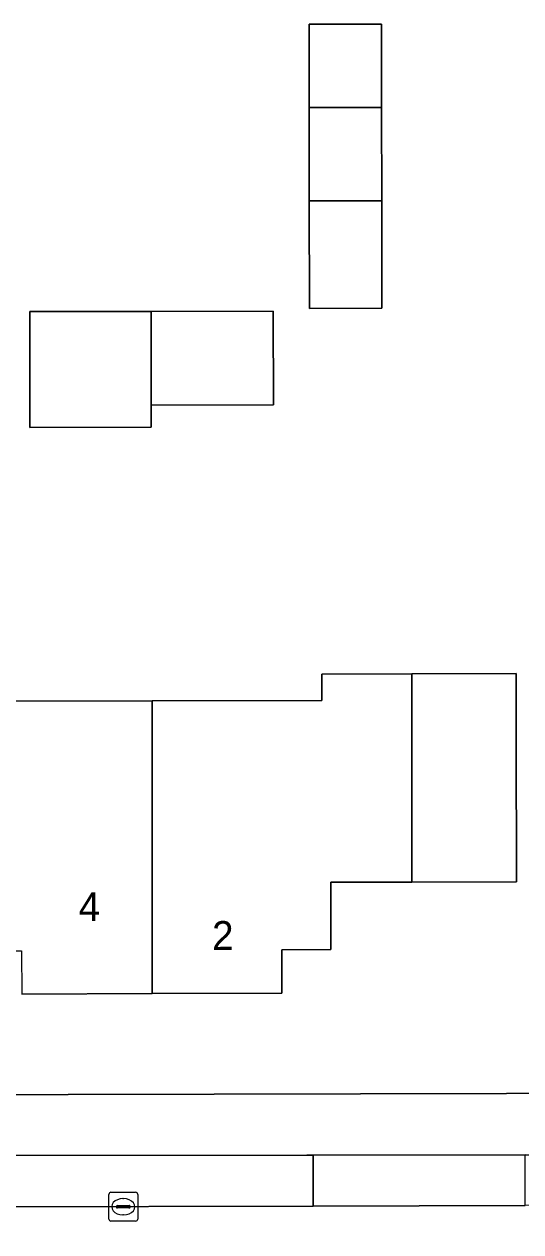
# Model space of a CAD drawing. Extents: x 160455 to 162082, y 388339 to 389736.
# Drawn here: x 160972.91 to 160990.1, y 388459.2 to 388501.02 of the extents above; entities that cross this region are included whole.
import ezdxf

# ---------------------------------------------------------------- set-up
doc = ezdxf.new("R2010")
doc.units = 0
for name, color, linetype in [('IMGEO_Erf', 7, 'Continuous'), ('IMGEO_Kolk', 7, 'Continuous'), ('IMGEO_Muur', 7, 'Continuous'), ('IMGEO_Pand', 7, 'Continuous'), ('IMGEO_Pand_nummerreeks', 7, 'Continuous'), ('IMGEO_Parkeervlak_open', 7, 'Continuous'), ('IMGEO_Rijbaan_lokaal_open', 7, 'Continuous'), ('IMGEO_Voetpad_open', 7, 'Continuous')]:
    doc.layers.add(name, color=color, linetype=linetype)

msp = doc.modelspace()

# ---------------------------------------------------------------- linework, layer by layer
at = {"layer": 'IMGEO_Erf'}
for points in [[(160985.287, 388494.904), (160985.293, 388491.181), (160982.786, 388491.177), (160982.78, 388494.904), (160982.775, 388498.125), (160982.772, 388501.016), (160985.279, 388501.016), (160985.282, 388498.128)], [(160981.536, 388491.078), (160981.541, 388487.832), (160977.31, 388487.826), (160977.311, 388487.063), (160973.113, 388487.056), (160973.107, 388491.065), (160977.305, 388491.072)]]:
    msp.add_lwpolyline(points, close=True, dxfattribs=at)
for points in [[(160971.454, 388477.577), (160977.344, 388477.591), (160983.214, 388477.605), (160983.212, 388478.515), (160986.332, 388478.522), (160989.942, 388478.531), (160989.947, 388476.322), (160989.959, 388471.322), (160986.334, 388471.314), (160983.525, 388471.308), (160983.527, 388468.978), (160981.825, 388468.971), (160981.831, 388467.473), (160977.341, 388467.452), (160972.831, 388467.431)], [(160954.202, 388463.916), (160989.602, 388463.995), (161000.033, 388464.037), (161013.406, 388464.055)]]:
    msp.add_lwpolyline(points, dxfattribs=at)
at = {"layer": 'IMGEO_Kolk'}
for p, q in [((160975.917, 388460.575), (160976.769, 388460.575)), ((160975.842, 388459.649), (160975.842, 388460.501)), ((160976.144, 388460.118), (160976.542, 388460.118)), ((160976.33, 388460.355), (160976.355, 388460.355)), ((160976.843, 388460.501), (160976.843, 388459.649)), ((160976.101, 388460.069), (160976.101, 388460.081)), ((160976.539, 388460.032), (160976.141, 388460.032)), ((160976.353, 388459.795), (160976.328, 388459.795)), ((160976.585, 388460.081), (160976.585, 388460.069)), ((160976.769, 388459.575), (160975.917, 388459.575))]:
    msp.add_line(p, q, dxfattribs=at)
for points in [[(160975.917, 388460.575), (160976.769, 388460.575)], [(160975.842, 388459.649), (160975.842, 388460.501)], [(160976.843, 388460.501), (160976.843, 388459.649)], [(160976.769, 388459.575), (160975.917, 388459.575)]]:
    msp.add_lwpolyline(points, dxfattribs=at)
for centre, radius, start, end in [((160975.919, 388460.499), 0.0765, 91.552, 178.448), ((160975.919, 388460.499), 0.0765, 91.552, 178.448), ((160976.767, 388460.499), 0.0765, 1.552, 88.448), ((160976.767, 388460.499), 0.0765, 1.552, 88.448), ((160976.141, 388460.078), 0.0403, 85.8775, 175.7526), ((160976.546, 388460.08), 0.0386, 1.7309, 96.639), ((160976.138, 388460.068), 0.0366, 178.938, 274.7102), ((160976.542, 388460.075), 0.043, 264.8664, 352.4533), ((160975.919, 388459.651), 0.0765, 181.552, 268.448), ((160975.919, 388459.651), 0.0765, 181.552, 268.448), ((160976.767, 388459.651), 0.0765, 271.552, 358.448), ((160976.767, 388459.651), 0.0765, 271.552, 358.448)]:
    msp.add_arc(centre, radius, start, end, dxfattribs=at)
for centre, major_axis, ratio, start_param, end_param in [((160976.329, 388460.075), (-0.387, 0.002), 0.722429, 4.712389, 7.853982), ((160976.354, 388460.075), (-0.39, 0.002), 0.717154, 1.570796, 4.712389)]:
    msp.add_ellipse(centre, major_axis=major_axis, ratio=ratio, start_param=start_param, end_param=end_param, dxfattribs=at)
at = {"layer": 'IMGEO_Muur'}
msp.add_lwpolyline([(160989.602, 388463.995), (161000.033, 388464.037)], dxfattribs=at)
at = {"layer": 'IMGEO_Pand'}
for points in [[(160985.282, 388498.128), (160985.279, 388501.016), (160982.772, 388501.016), (160982.775, 388498.125)], [(160985.282, 388498.128), (160982.775, 388498.125), (160982.78, 388494.904), (160985.287, 388494.904)], [(160985.287, 388494.904), (160982.78, 388494.904), (160982.786, 388491.177), (160985.293, 388491.181)], [(160977.305, 388491.072), (160973.107, 388491.065), (160973.113, 388487.056), (160977.311, 388487.063), (160977.31, 388487.826)], [(160977.305, 388491.072), (160977.31, 388487.826), (160981.541, 388487.832), (160981.536, 388491.078)], [(160977.341, 388467.452), (160981.831, 388467.473), (160981.825, 388468.971), (160983.527, 388468.978), (160983.525, 388471.308), (160986.334, 388471.314), (160986.332, 388478.522), (160983.212, 388478.515), (160983.214, 388477.605), (160977.344, 388477.591)], [(160989.947, 388476.322), (160989.942, 388478.531), (160986.332, 388478.522), (160986.334, 388471.314), (160989.959, 388471.322)], [(160968.321, 388478.469), (160968.337, 388471.234), (160971.125, 388471.225), (160971.125, 388468.933), (160972.825, 388468.939), (160972.831, 388467.431), (160977.341, 388467.452), (160977.344, 388477.591), (160971.454, 388477.577), (160971.451, 388478.476), (160970.191, 388478.473)]]:
    msp.add_lwpolyline(points, close=True, dxfattribs=at)
at = {"layer": 'IMGEO_Parkeervlak_open'}
for points in [[(160982.914, 388461.859), (160982.699, 388461.859), (160971.824, 388461.853), (160971.515, 388461.851), (160971.515, 388460.073), (160982.917, 388460.099)], [(160990.248, 388461.875), (160982.914, 388461.859), (160982.917, 388460.099), (160990.252, 388460.115)]]:
    msp.add_lwpolyline(points, close=True, dxfattribs=at)
at = {"layer": 'IMGEO_Rijbaan_lokaal_open'}
msp.add_lwpolyline([(161010.987, 388460.172), (161000, 388460.137), (160990.252, 388460.115), (160982.917, 388460.099), (160971.515, 388460.073), (160965.031, 388460.059), (160960.748, 388460.049), (160957.699, 388460.072), (160957.625, 388455.513), (160963.891, 388455.525), (160970.528, 388455.538), (160981.957, 388455.561), (160989.227, 388455.575), (161000, 388455.596), (161011.014, 388455.617)], close=True, dxfattribs=at)
at = {"layer": 'IMGEO_Voetpad_open'}
for points in [[(161013.406, 388464.055), (161000.033, 388464.037), (160989.602, 388463.995), (160954.202, 388463.916), (160953.205, 388461.674)], [(160960.315, 388461.814), (160965.027, 388461.82), (160971.515, 388461.851), (160971.824, 388461.853), (160982.699, 388461.859), (160982.914, 388461.859), (160990.248, 388461.875), (160990.688, 388461.876), (161000, 388461.908), (161008.283, 388461.936)]]:
    msp.add_lwpolyline(points, dxfattribs=at)

# ---------------------------------------------------------------- texts
at = {"layer": 'IMGEO_Pand_nummerreeks'}
for s, rotation, p in [('4', 0.2674, (160974.799, 388469.96)), ('2', 0.268, (160979.419, 388468.962))]:
    msp.add_text(s, height=1, rotation=rotation, dxfattribs=at).set_placement(p)

doc.saveas('drawing.dxf')
